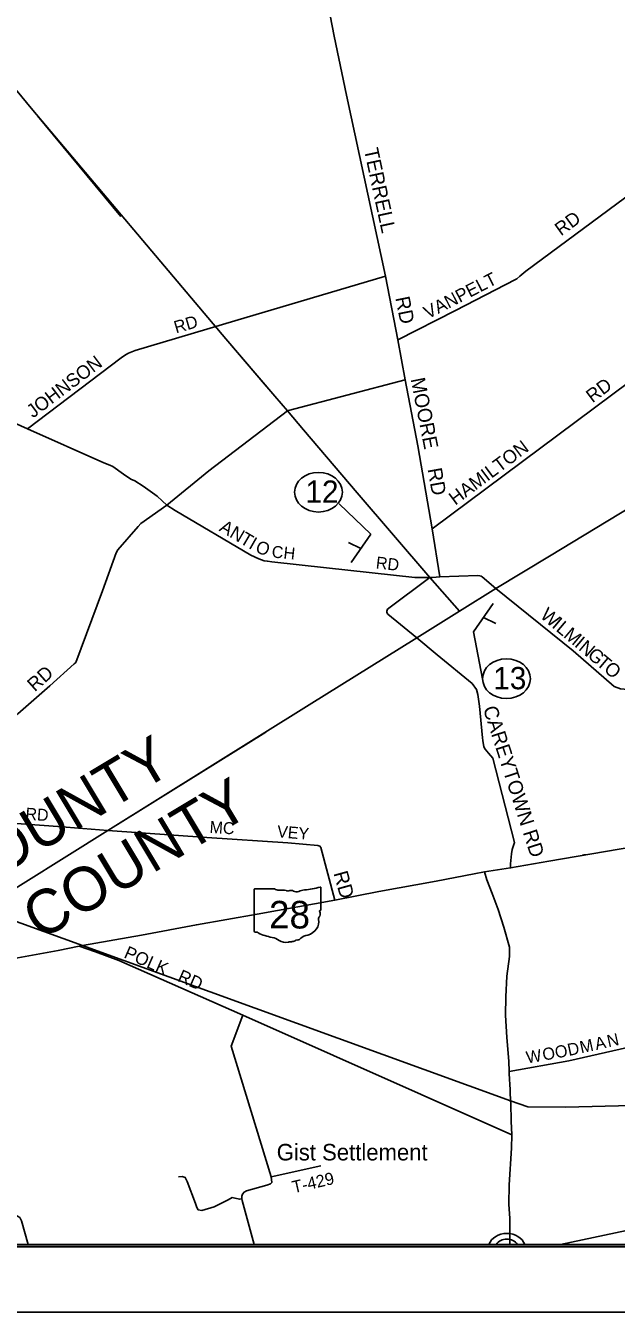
# Model space of a CAD drawing. Extents: x 0 to 784, y 0 to 440.
# Drawn here: x 176.2 to 266.5, y 0 to 196.7 of the extents above; entities that cross this region are included whole.
import ezdxf

# ---------------------------------------------------------------- set-up
doc = ezdxf.new("R2010")
doc.units = 0
for name, color, linetype in [('Default', 7, 'Continuous'), ('SH_Border', 7, 'Continuous'), ('SH_Cut_Line', 7, 'Continuous')]:
    doc.layers.add(name, color=color, linetype=linetype)

msp = doc.modelspace()

# ---------------------------------------------------------------- linework, layer by layer
at = {"layer": 'Default'}
for p, q in [((224.09, 123.59), (228.95, 118.94)), ((225.93, 114.61), (228.95, 118.94)), ((227.44, 116.78), (225.54, 117.68)), ((247.67, 108.36), (244.66, 104.03)), ((246.17, 106.2), (248.07, 105.29)), ((246.03, 96.86), (244.66, 104.03)), ((211.12, 64.62), (211.12, 58.22)), ((214.21, 64.73), (211.23, 64.73)), ((221.31, 61.54), (221.31, 64.89)), ((221.31, 61.54), (221.31, 61.54)), ((392.02, 10.38), (128.62, 10.38)), ((247, 10.38), (252.49, 10.38)), ((248.13, 10.38), (251.36, 10.38))]:
    msp.add_line(p, q, dxfattribs=at)
msp.add_lwpolyline([(31.33, 429.99), (465.77, 429.99), (465.77, 10.05), (31.33, 10.05)], close=True, dxfattribs=at)
for points in [[(177.35, 316.06), (100.83, 299.13), (35.04, 284.49), (73.81, 267.89), (110.52, 252.18), (116.33, 249.66), (125.29, 245.78), (143.28, 224.29), (163.94, 199.83), (177.25, 183.75)], [(234.21, 142.56), (233.08, 148.65), (231.19, 158.37), (225.22, 186.04), (223.35, 195.1), (219.56, 214.65)], [(177.25, 183.75), (206.75, 148.79)], [(252.68, 159.16), (286.74, 184.37)], [(177.96, 182.89), (190.69, 167.51)], [(238.35, 119.77), (293.4, 160.8)], [(208.16, 151.55), (231.19, 158.37)], [(233.08, 148.65), (241.9, 153.12), (251.05, 157.87), (251.26, 157.98), (251.73, 158.37), (252.68, 159.16)], [(328.56, 159.01), (324.71, 156.77), (317.42, 152.51), (299.29, 141.61), (298.95, 141.4), (256.26, 115.59)], [(176.45, 135.07), (190.78, 145.9), (191.44, 146.37), (191.88, 146.63), (192.88, 147.01), (208.16, 151.55)], [(206.75, 148.79), (213, 141.5)], [(206.75, 148.79), (214.26, 140.04)], [(197.74, 123.4), (197.74, 123.4), (197.04, 124.07), (196.25, 124.74), (194.14, 126.31), (192.83, 127.08), (192.25, 127.37), (191.14, 128.13), (189.48, 129.28), (189.02, 129.5), (188.12, 129.85), (176.45, 135.07), (171.86, 137.11), (169.57, 138.11), (168.61, 138.65), (160.01, 143.57), (159.12, 144.01), (158.86, 144.09), (158.05, 144.28), (143.84, 146.54), (142.19, 146.79), (141.26, 146.9), (134.84, 147.23)], [(216.37, 137.86), (234.21, 142.56)], [(239.51, 112.43), (238.35, 119.77), (236.14, 132.44), (234.21, 142.56)], [(214.26, 140.04), (216.18, 137.8), (216.49, 137.44)], [(214.26, 140.04), (216.18, 137.8), (218.66, 134.91)], [(204.15, 128.62), (216.18, 137.8), (216.37, 137.86)], [(218.66, 134.91), (219.11, 134.38)], [(218.66, 134.91), (226.87, 125.29)], [(197.74, 123.4), (204.15, 128.62)], [(226.87, 125.29), (237.97, 112.31), (242.49, 107.16), (235.98, 103.1), (219.54, 92.84)], [(187.92, 110.31), (190.01, 116.09), (190.25, 116.55), (193.35, 120.14), (193.77, 120.6), (197.74, 123.4)], [(237.97, 112.31), (235.7, 112.34), (222.19, 113.81), (213.82, 114.72), (213.13, 114.8), (212.65, 114.88), (211.81, 115.16), (210.59, 115.74), (199.02, 122.57), (197.74, 123.4)], [(256.26, 115.59), (248.09, 110.65), (242.49, 107.16), (235.98, 103.1), (219.54, 92.84)], [(256.26, 115.59), (248.09, 110.65), (242.49, 107.16), (235.98, 103.1), (219.54, 92.84)], [(256.26, 115.59), (248.09, 110.65), (242.49, 107.16), (235.98, 103.1), (219.54, 92.84)], [(219.54, 92.84), (235.98, 103.1), (242.49, 107.16), (248.09, 110.65), (256.26, 115.59)], [(219.54, 92.84), (235.98, 103.1), (242.49, 107.16), (248.09, 110.65), (256.26, 115.59)], [(219.54, 92.84), (235.98, 103.1), (242.49, 107.16), (248.09, 110.65), (256.26, 115.59)], [(235.98, 103.1), (231.57, 106.74), (231.39, 106.99), (231.37, 107.19), (231.49, 107.46), (237.97, 112.31)], [(248.09, 110.65), (245.97, 112.43), (245.8, 112.53), (245.61, 112.59), (245.32, 112.61), (239.51, 112.43), (238.37, 112.34), (237.97, 112.31)], [(147.71, 66.75), (147.72, 66.76), (148.76, 67.61), (150.74, 69.3), (151.56, 70.09), (157.53, 76.13), (160.34, 78.72), (163.74, 81.42), (167.68, 84.98), (174.95, 91.46), (179.83, 95.79), (183.57, 99.12), (183.81, 99.35), (187.92, 110.31)], [(303.45, 88.57), (302.92, 89.19), (301.74, 90.77), (300.85, 91.93), (299.93, 92.71), (298.86, 93.27), (297.7, 93.64), (296.21, 94.08), (295.21, 94.32), (294.09, 94.31), (292.08, 94.21), (290.78, 94.14), (287.05, 94.23), (271.13, 94.94), (268.28, 95.18), (267.12, 95.31), (266.15, 95.66), (259.9, 101.1), (248.09, 110.65)], [(246.04, 87.84), (245.55, 92.66), (245.33, 94.42), (245.13, 95.21), (244.44, 96.11), (239.11, 100.48), (235.98, 103.1)], [(219.54, 92.84), (188.74, 73.63), (169.46, 61.61), (151.92, 50.67), (138.57, 42.34), (136.27, 40.91), (134.39, 39.73), (120.96, 31.36), (103, 20.15), (102.72, 19.97), (87.73, 10.38)], [(212.87, 88.69), (188.74, 73.63), (169.46, 61.61), (151.92, 50.67), (138.57, 42.34), (136.27, 40.91), (134.39, 39.73), (120.96, 31.36), (103, 20.15), (102.72, 19.97), (87.73, 10.38)], [(212.87, 88.69), (188.74, 73.63), (169.46, 61.61), (151.92, 50.67), (138.57, 42.34), (136.27, 40.91), (134.39, 39.73), (120.96, 31.36), (103, 20.15), (102.72, 19.97), (87.73, 10.38)], [(212.87, 88.69), (188.74, 73.63), (169.46, 61.61), (151.92, 50.67), (138.57, 42.34), (136.27, 40.91), (134.39, 39.73), (120.96, 31.36), (103, 20.15), (102.72, 19.97), (87.73, 10.38)], [(341, 26.87), (337.2, 27.44), (303.55, 32.49), (303.35, 32.48), (258.73, 31.34), (252.96, 31.39), (250.33, 32.34), (184.83, 56.05), (169.46, 61.61), (188.74, 73.63), (212.87, 88.69)], [(247.61, 84.72), (246.96, 85.45), (246.45, 86.06), (246.23, 86.45), (246.08, 87.41), (246.04, 87.84)], [(250.33, 67.93), (250.32, 68.56), (250.48, 70.07), (250.57, 70.75), (250.92, 71.8), (247.61, 84.72)], [(157.53, 76.13), (160.24, 75.92), (171.22, 74.98), (181.1, 74.25), (188.74, 73.63)], [(223.42, 63.02), (221.29, 71.06), (221.16, 71.24), (220.82, 71.38), (216.26, 71.78), (203.84, 72.6), (188.74, 73.63)], [(151.92, 50.67), (160.67, 51.86), (169.13, 53.18), (172.73, 53.8), (181.11, 55.3), (184.36, 55.97), (184.83, 56.05), (193.87, 57.67), (202.27, 59.24), (211.56, 60.88), (223.42, 63.02), (230.19, 64.31), (238.93, 65.91), (244.75, 67.02), (246.32, 67.31), (250.33, 67.93), (256.18, 68.96), (273.5, 71.94)], [(261.31, 69.88), (261.54, 69.94), (261.71, 69.94), (261.85, 69.93)], [(250.19, 35.14), (250.19, 35.14), (250.18, 35.34), (250.1, 36.81), (250.03, 38.4), (249.77, 41.98), (249.55, 45.43), (249.61, 48.23), (249.77, 51.36), (250.16, 54.38), (250.17, 55.8), (249.3, 58.85), (248.44, 61.56), (247.49, 64.04), (246.68, 66.09), (246.32, 67.31)], [(169.46, 61.61), (184.83, 56.05), (250.33, 32.34), (252.96, 31.39), (258.73, 31.34), (303.35, 32.48)], [(184.36, 55.97), (186.85, 55.12), (190.38, 53.78), (209.37, 45.43), (250.53, 27.12)], [(211.08, 10.38), (209.25, 17.08), (209.2, 17.33), (209.22, 17.75), (209.32, 18.07), (209.55, 18.38), (209.94, 18.57), (213.04, 19.42), (213.61, 19.64), (213.79, 19.83), (213.7, 20.68), (207.57, 40.68), (209.37, 45.43)], [(250.1, 36.81), (259.23, 38.43), (270.46, 40.97), (278.78, 42.57)], [(134.39, 39.73), (136.09, 39.24), (138.77, 38.29), (140.96, 37.51), (142.26, 36.99), (143.24, 36.59), (143.64, 36.38), (144.37, 35.91), (146.55, 34.37), (151.06, 31.04), (162.12, 22.47), (171.48, 15.25), (171.85, 15.08), (172.19, 14.95), (172.48, 14.89), (172.83, 14.91), (173.43, 14.92), (173.98, 14.97), (174.43, 14.9), (174.93, 14.69), (175.25, 14.51), (175.51, 13.99), (176.56, 10.38)], [(250.21, 10.38), (250.2, 14.34), (250.06, 16.53), (250.11, 19.47), (250.47, 25.08), (250.53, 27.12), (250.39, 29.2), (250.35, 31.96), (250.33, 32.34), (250.19, 35.14)], [(257.97, 10.38), (279.82, 15.02), (301.48, 19.39), (304.2, 19.91), (306.97, 20.45), (322.05, 23.3), (333.25, 25.2), (336.79, 25.85)], [(213.7, 20.68), (221.29, 22.41)], [(199.53, 20.71), (200.07, 20.73), (200.57, 20.59), (200.87, 20.01), (202.11, 16.61), (202.34, 16), (202.55, 15.64), (203.12, 15.58), (204.97, 16.12), (206.31, 16.76), (207.14, 17.19), (207.72, 17.53), (208.15, 17.46), (208.89, 17.29), (209.2, 17.33)]]:
    msp.add_lwpolyline(points, dxfattribs=at)
for centre in [(220.94, 125.37), (249.69, 96.86)]:
    msp.add_ellipse(centre, major_axis=(3.66, 0), ratio=0.82844, dxfattribs=at)
for centre, major_axis, start_param, end_param in [((217.68, 73.46), (10.8, 0), 4.814394, 5.042369), ((221.2, 64.91), (0.113, 0), 6.141152, 7.989035), ((211.24, 64.64), (0.118, 0), 1.712693, 3.28349), ((214.92, 65.48), (1.14, 0), 4.042523, 4.731795), ((215.3, 61.14), (4.11, 0), 1.404758, 1.657858), ((216.23, 64.67), (0.33, 0), 3.836095, 5.185415), ((216.72, 63.93), (0.686, 0), 0.950623, 2.079405), ((217.6, 64.95), (0.826, 0), 4.081561, 5.145723), ((219.06, 62.78), (2.17, 0), 1.699011, 2.107814), ((221.28, 61.3), (0.175, 0), 1.883978, 3.671073), ((220.17, 60.87), (1.05, 0), 5.934695, 6.695948), ((221.19, 61.53), (0.121, 0), 5.05454, 6.418171), ((218.29, 59.71), (2.7, 0), 5.101752, 6.440018), ((221.72, 60.14), (0.766, 0), 2.387724, 3.262537), ((211.24, 58.21), (0.119, 0), 3.00124, 4.508301), ((211.26, 58.86), (0.908, 0), 4.665946, 4.897461), ((211.45, 57.85), (0.328, 0), 0.519207, 1.627899), ((215.58, 63.6), (7.8, 0), 4.195997, 4.488961), ((213.26, 55.34), (2.44, 0), 0.823519, 1.323587), ((217.55, 57.6), (0.873, 0), 4.937069, 5.64225), ((219.43, 56.42), (1.48, 0), 1.647645, 2.488434), ((215.9, 57.82), (1.55, 0), 4.026481, 4.996735), ((216.79, 55.6), (1.27, 0), 1.495662, 1.94098), ((216.9, 57.34), (0.825, 0), 4.691044, 5.507374), ((217.65, 56.72), (0.232, 0), 1.147584, 2.315152), ((249.75, 9.68), (2.87, 0), 0.298989, 2.842603), ((249.75, 9.68), (1.82, 0), 0.48326, 2.658333)]:
    msp.add_ellipse(centre, major_axis=major_axis, ratio=0.82844, start_param=start_param, end_param=end_param, dxfattribs=at)
at = {"layer": 'SH_Border'}
msp.add_lwpolyline([(30, 430), (670, 430), (670, 10), (30, 10)], close=True, dxfattribs=at)
at = {"layer": 'SH_Cut_Line'}
msp.add_lwpolyline([(0, 0), (680, 0), (680, 440), (0, 440)], close=True, dxfattribs=at)

# ---------------------------------------------------------------- texts
at = {"layer": 'Default'}
for s, height, rotation, p in [('TERRELL', 2.195, 282.1115, (227.88, 177.75)), ('RD', 2.058, 35.8926, (258.03, 164.47)), ('VANPELT', 1.983, 27.1286, (237.67, 151.8)), ('RD', 2.195, 281.3735, (232.68, 155.08)), ('RD', 1.89, 16.51, (199.16, 149.62)), ('JOHNSON', 2.067, 37.0434, (177.28, 136.62)), ('MOORE', 2.195, 281.039, (235.03, 142.67)), ('RD', 2.066, 36.9205, (262.84, 138.94)), ('HAMILTON', 2.064, 36.7083, (241.86, 123.29)), ('RD', 2.195, 280.1162, (237.61, 128.9)), ('A', 2.01, 329.4729, (205.62, 119.53)), ('N', 2.01, 329.4738, (207.2, 118.6)), ('T', 2.01, 329.5331, (208.77, 117.67)), ('I', 2.01, 330.1299, (210.13, 116.87)), ('O', 1.95, 336.9606, (211.14, 116.31)), ('C', 1.82, 355.8885, (213.75, 115.37)), ('H', 1.83, 353.8124, (215.52, 115.24)), ('RD', 1.831, 353.424, (229.65, 113.73)), ('W', 2.09, 319.852, (254.72, 106.3)), ('I', 2.09, 319.8497, (256.51, 104.8)), ('L', 2.09, 319.8542, (257.14, 104.27)), ('M', 2.09, 319.8516, (258.29, 103.3)), ('I', 2.09, 319.8497, (259.96, 101.89)), ('N', 2.09, 319.8536, (260.59, 101.35)), ('G', 2.09, 319.8507, (261.94, 100.21)), ('T', 2.09, 319.8542, (263.3, 99.07)), ('RD', 2.1, 41.6856, (177.55, 94.77)), ('O', 2.09, 319.957, (264.45, 98.1)), ('CAREYTOWN RD', 2.195, 287.8637, (246.07, 92.31)), ('CLINTON COUNTY', 6.7214, 30.946, (130.5, 41.63)), ('HIGHLAND COUNTY', 6.7214, 30.946, (136.41, 31.57)), ('RD', 1.823, 355.9156, (176.08, 75.33)), ('MC', 1.822, 356.3543, (204.25, 73.29)), ('VEY', 1.825, 355.2636, (214.56, 72.62)), ('RD', 2.194, 285.5216, (223.22, 67.13)), ('POLK', 1.951, 336.3545, (191.05, 54.28)), ('RD', 1.952, 336.318, (199.26, 50.68)), ('M', 1.86, 12.4935, (261.12, 39.57)), ('A', 1.86, 12.4907, (263.43, 40.08)), ('N', 1.86, 12.4944, (265.29, 40.5)), ('W', 1.85, 10.0325, (252.88, 38.02)), ('O', 1.85, 10.0423, (255.36, 38.46)), ('O', 1.85, 10.7145, (257.28, 38.8)), ('D', 1.86, 12.0165, (259.23, 39.17)), ('Gist Settlement', 2.5254, 0, (214.55, 23.21)), ('T-429', 1.864, 12.8573, (217.14, 18.19))]:
    msp.add_text(s, height=height, rotation=rotation, dxfattribs=at).set_placement(p)
for s, height, p in [('12', 3.406, (218.94, 123.75)), ('13', 3.406, (247.67, 95.24)), ('28', 4.219, (213.37, 58.67))]:
    msp.add_text(s, height=height, dxfattribs=at).set_placement(p)

doc.saveas('drawing.dxf')
